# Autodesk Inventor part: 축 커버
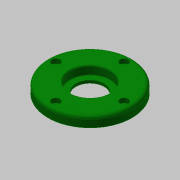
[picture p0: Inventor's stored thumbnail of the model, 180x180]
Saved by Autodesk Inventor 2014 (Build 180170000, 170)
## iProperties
Created: 2015-10
Part Number: 축 커버
Document SubType Name: Modeling
Designer: mdu
Density: 1 g/cm^3
Material: 일반
Appearance: Dark Green
Mass: 42.4472 g
Surface Area: 136.578 cm^2
Volume: 42.4472 cm^3
Author: mdu
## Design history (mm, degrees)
sketch "스케치1"
  geometry: C1 r 40 at (0, 0) reference; C2 r 26 at (0, 0) reference; 1 further point
  node "참조1"
  node "참조2"
extrude "돌출1" new body sketch "스케치1" distance "d0" = 10; taper "d1" = 0 deg
extrude "돌출2" join sketch "스케치1" distance "d2" = 4; taper "d3" = 0 deg
hole "구멍1" diameter "d6" = 27; stored, may be unused: countersink angle "d10" = 90 deg, drill point angle "d12" = 118 deg; dims "d7" = 6, "d8" = 38, "d9" = 8.3, "d11" = 8, "d33" = 10, "d34" = 10
sketch "스케치2"
  geometry: C1 r 20 at (0, 0); 1 further point
  constraints: 1 centre point, 1 coincident
  dimensions: "d13" = 40 diameter of C1
extrude "돌출3" cut sketch "스케치2" distance "d14" = 3; taper "d15" = 0 deg
sketch "스케치3"
  geometry: C1 r 1.621 at (0, 32.5) reference; 1 further point
hole "구멍2" sketch "스케치3" at (0, 32.5) diameter "d16" = 4.5; stored, may be unused: countersink angle "d20" = 90 deg, drill point angle "d22" = 118 deg; dims "d17" = 6, "d18" = 8, "d19" = 4.4, "d21" = 8
fillet "모깎기1" dims "d26" = 3, "d27" = 0.3
chamfer "모따기1" distance "d28" = 1; stored, may be unused: second distance "d29" = 2, angle "d30" = 45 deg
chamfer "모따기2" distance "d31" = 0.8; stored, may be unused: second distance "d32" = 2, angle "d35" = 30 deg
node "솔리드1"
pattern_circular "원형 패턴1" dims angle "d24" = 360 deg
node "참조3"
